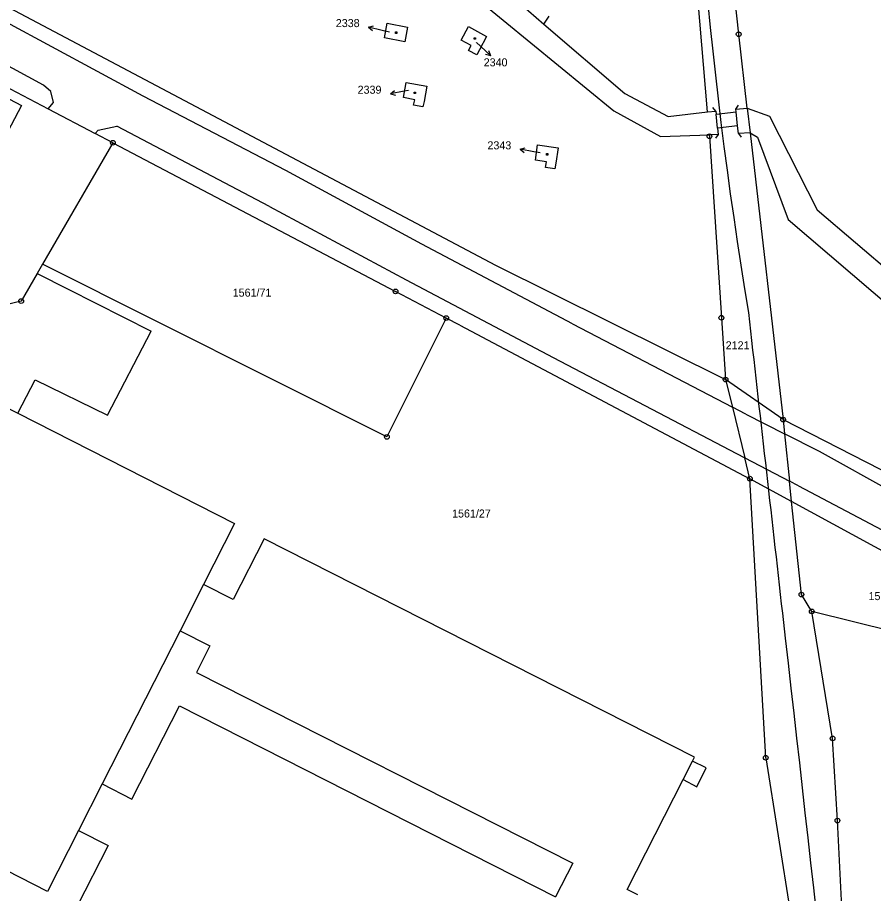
# Model space of a CAD drawing. Extents: x -795483 to -789093, y -1112258 to -1108741.
# Drawn here: x -792761.3 to -792579.5, y -1110577.6 to -1110391.5 of the extents above; entities that cross this region are included whole.
import ezdxf

# ---------------------------------------------------------------- set-up
doc = ezdxf.new("R2010")
doc.units = 0
for name, color, linetype in [('Komunikace', 7, 'Continuous'), ('Popis vodovodních řadů', 7, 'Continuous'), ('Vrstva 1', 7, 'Continuous'), ('Vrstva 10', 7, 'Continuous'), ('Vrstva 14', 7, 'Continuous'), ('Vrstva 15', 7, 'Continuous'), ('Vrstva 16', 7, 'Continuous'), ('Vrstva 2', 7, 'Continuous'), ('Vrstva 25', 7, 'Continuous'), ('Vrstva 28', 7, 'Continuous')]:
    doc.layers.add(name, color=color, linetype=linetype)

msp = doc.modelspace()

# ---------------------------------------------------------------- linework, layer by layer
at = {"layer": 'Komunikace'}
for p, q in [((-792682.33, -1110394.57), (-792683.89, -1110394.2)), ((-792663.85, -1110396.79), (-792663.02, -1110397.58)), ((-792678.29, -1110406.98), (-792679.19, -1110407.14)), ((-792650.34, -1110420.22), (-792651.65, -1110419.99))]:
    msp.add_line(p, q, dxfattribs=at)
at = {"layer": 'Popis vodovodních řadů'}
for p, q in [((-792613.01, -1110411.35), (-792613.66, -1110410.6)), ((-792608.74, -1110410.94), (-792608.23, -1110410.09)), ((-792612.51, -1110416.31), (-792613.08, -1110417.12)), ((-792608.23, -1110416.1), (-792607.66, -1110416.91))]:
    msp.add_line(p, q, dxfattribs=at)
at = {"layer": 'Vrstva 1'}
for p, q in [((-792608.17, -1110395.02), (-792615.38, -1110323.92)), ((-792614.81, -1110411.53), (-792620.21, -1110347.82)), ((-792681.61, -1110364.96), (-792649.52, -1110392.89)), ((-792780.58, -1110380.1), (-792659.8, -1110444.12)), ((-792666.12, -1110385.5), (-792634.65, -1110411.27)), ((-792649.52, -1110392.89), (-792648.42, -1110391.17)), ((-792683.39, -1110395.82), (-792682.79, -1110392.67)), ((-792682.79, -1110392.67), (-792678.49, -1110393.51)), ((-792678.49, -1110393.51), (-792679.09, -1110396.64)), ((-792667.12, -1110396.3), (-792665.58, -1110393.41)), ((-792665.58, -1110393.41), (-792661.7, -1110395.49)), ((-792649.52, -1110392.89), (-792632.37, -1110407.62)), ((-792679.09, -1110396.64), (-792683.39, -1110395.82)), ((-792661.7, -1110395.49), (-792663.23, -1110398.37)), ((-792606.36, -1110410.71), (-792608.17, -1110395.02)), ((-792781.4, -1110396.88), (-792754.82, -1110410.86)), ((-792665, -1110397.43), (-792667.12, -1110396.3)), ((-792665.56, -1110398.49), (-792665, -1110397.43)), ((-792663.79, -1110399.43), (-792665.56, -1110398.49)), ((-792663.23, -1110398.37), (-792663.79, -1110399.43)), ((-792679.35, -1110408.5), (-792678.76, -1110405.29)), ((-792678.76, -1110405.29), (-792674.41, -1110406.08)), ((-792674.41, -1110406.08), (-792674.99, -1110409.3)), ((-792676.97, -1110408.94), (-792679.35, -1110408.5)), ((-792632.37, -1110407.62), (-792623.11, -1110412.52)), ((-792677.19, -1110410.12), (-792676.97, -1110408.94)), ((-792675.21, -1110410.48), (-792677.19, -1110410.12)), ((-792674.99, -1110409.3), (-792675.21, -1110410.48)), ((-792608.74, -1110410.94), (-792606.36, -1110410.71)), ((-792606.36, -1110410.71), (-792601.62, -1110412.42)), ((-792606.36, -1110410.71), (-792605.76, -1110415.98)), ((-792754.82, -1110410.86), (-792744.86, -1110416.1)), ((-792634.65, -1110411.27), (-792624.78, -1110416.77)), ((-792623.11, -1110412.52), (-792614.81, -1110411.53)), ((-792614.81, -1110411.53), (-792613.01, -1110411.35)), ((-792613.01, -1110411.35), (-792612.94, -1110412.04)), ((-792612.94, -1110412.04), (-792608.68, -1110411.53)), ((-792608.68, -1110411.53), (-792608.74, -1110410.94)), ((-792601.62, -1110412.42), (-792591.51, -1110432.33)), ((-792741.07, -1110418.09), (-792744.86, -1110416.1)), ((-792612.51, -1110416.31), (-792614.4, -1110416.41)), ((-792608.39, -1110414.49), (-792612.65, -1110414.98)), ((-792612.65, -1110414.98), (-792612.51, -1110416.31)), ((-792608.23, -1110416.1), (-792608.39, -1110414.49)), ((-792605.76, -1110415.98), (-792608.23, -1110416.1)), ((-792605.76, -1110415.98), (-792604.19, -1110416.91)), ((-792605.76, -1110415.98), (-792598.74, -1110476.89)), ((-792741.07, -1110418.09), (-792756.01, -1110443.91)), ((-792741.07, -1110418.09), (-792681.03, -1110449.67)), ((-792624.78, -1110416.77), (-792614.4, -1110416.41)), ((-792614.4, -1110416.41), (-792614.37, -1110416.71)), ((-792614.37, -1110416.71), (-792611.85, -1110455.28)), ((-792604.19, -1110416.91), (-792597.68, -1110434.36)), ((-792651.35, -1110421.79), (-792650.87, -1110418.51)), ((-792650.87, -1110418.51), (-792646.52, -1110419.16)), ((-792646.52, -1110419.16), (-792647, -1110422.44)), ((-792648.99, -1110422.14), (-792651.35, -1110421.79)), ((-792649.17, -1110423.34), (-792648.99, -1110422.14)), ((-792647.18, -1110423.63), (-792649.17, -1110423.34)), ((-792647, -1110422.44), (-792647.18, -1110423.63)), ((-792591.51, -1110432.33), (-792497.5, -1110512.53)), ((-792597.68, -1110434.36), (-792501.08, -1110517.07)), ((-792756.01, -1110443.91), (-792757.16, -1110445.89)), ((-792682.88, -1110480.58), (-792756.01, -1110443.91)), ((-792659.8, -1110444.12), (-792610.94, -1110468.39)), ((-792757.16, -1110445.89), (-792760.54, -1110451.74)), ((-792757.16, -1110445.89), (-792750.58, -1110449.21)), ((-792750.58, -1110449.21), (-792732.96, -1110458.09)), ((-792670.27, -1110455.33), (-792681.03, -1110449.67)), ((-792760.54, -1110451.74), (-792783.32, -1110457.02)), ((-792670.27, -1110455.33), (-792682.88, -1110480.58)), ((-792667.41, -1110456.84), (-792670.27, -1110455.33)), ((-792611.85, -1110455.28), (-792610.94, -1110468.39)), ((-792667.41, -1110456.84), (-792605.8, -1110489.46)), ((-792742.2, -1110475.94), (-792732.96, -1110458.09)), ((-792761.23, -1110475.55), (-792757.59, -1110468.44)), ((-792757.59, -1110468.44), (-792742.2, -1110475.94)), ((-792610.94, -1110468.39), (-792609.51, -1110474.26)), ((-792768.36, -1110471.92), (-792761.23, -1110475.55)), ((-792761.23, -1110475.55), (-792715.21, -1110499)), ((-792609.51, -1110474.26), (-792606.89, -1110485.01)), ((-792598.74, -1110476.89), (-792553.17, -1110500.22)), ((-792598.74, -1110476.89), (-792598.42, -1110479.91)), ((-792598.42, -1110479.91), (-792597.37, -1110489.98)), ((-792605.8, -1110489.46), (-792606.89, -1110485.01)), ((-792602.43, -1110548.75), (-792605.8, -1110489.46)), ((-792596.92, -1110494.31), (-792605.8, -1110489.46)), ((-792596.92, -1110494.31), (-792597.37, -1110489.98)), ((-792521.65, -1110535.49), (-792596.92, -1110494.31)), ((-792594.86, -1110514.07), (-792596.92, -1110494.31)), ((-792715.21, -1110499), (-792721.79, -1110511.93)), ((-792708.94, -1110502.27), (-792715.49, -1110515.15)), ((-792617.55, -1110548.61), (-792708.94, -1110502.27)), ((-792721.79, -1110511.93), (-792726.81, -1110521.82)), ((-792715.49, -1110515.15), (-792721.79, -1110511.93)), ((-792592.65, -1110517.65), (-792594.86, -1110514.07)), ((-792521.65, -1110535.49), (-792592.65, -1110517.65)), ((-792588.22, -1110544.64), (-792592.65, -1110517.65)), ((-792726.81, -1110521.82), (-792743.32, -1110554.29)), ((-792587.19, -1110562.1), (-792588.22, -1110544.64)), ((-792617.98, -1110549.46), (-792617.55, -1110548.61)), ((-792615.07, -1110550.92), (-792617.98, -1110549.46)), ((-792602.43, -1110548.75), (-792592.15, -1110613.52)), ((-792617.03, -1110554.92), (-792615.07, -1110550.92)), ((-792631.85, -1110576.75), (-792619.99, -1110553.41)), ((-792619.99, -1110553.41), (-792617.03, -1110554.92)), ((-792743.32, -1110554.29), (-792748.36, -1110564.21)), ((-792585.02, -1110604.07), (-792587.19, -1110562.1)), ((-792748.36, -1110564.21), (-792742.08, -1110567.4)), ((-792742.08, -1110567.4), (-792748.62, -1110580.29)), ((-792629.58, -1110577.89), (-792631.85, -1110576.75))]:
    msp.add_line(p, q, dxfattribs=at)
msp.add_lwpolyline([(-792748.36, -1110564.21), (-792754.94, -1110577.15), (-792801.15, -1110553.55)], dxfattribs=at)
at = {"layer": 'Vrstva 10'}
for centre, radius, start, end in [((-791654.82, -1110295.97), 964.34, 179.75891, 189.43975), ((-568495.15, -1085164.41), 225533.35, 186.4382861, 186.4546222), ((-545938.95, -1082684.09), 248225.4, 186.4382139, 186.4776556)]:
    msp.add_arc(centre, radius, start, end, dxfattribs=at)
at = {"layer": 'Vrstva 16'}
for p, q in [((-792686.81, -1110393.51), (-792685.72, -1110393.25)), ((-792683.89, -1110394.2), (-792686.81, -1110393.51)), ((-792686.81, -1110393.51), (-792685.95, -1110394.23)), ((-792663.02, -1110397.58), (-792660.83, -1110399.64)), ((-792660.83, -1110399.64), (-792661.91, -1110399.31)), ((-792660.83, -1110399.64), (-792661.22, -1110398.59)), ((-792682.14, -1110407.67), (-792681.25, -1110407)), ((-792679.19, -1110407.14), (-792682.14, -1110407.67)), ((-792682.14, -1110407.67), (-792681.07, -1110407.98)), ((-792654.6, -1110419.48), (-792653.54, -1110419.16)), ((-792651.65, -1110419.99), (-792654.6, -1110419.48)), ((-792654.6, -1110419.48), (-792653.71, -1110420.14))]:
    msp.add_line(p, q, dxfattribs=at)
at = {"layer": 'Vrstva 2'}
for p, q in [((-792755.78, -1110405.83), (-792779.28, -1110393.19)), ((-792734.65, -1110408.19), (-792763.7, -1110392.48)), ((-792770.97, -1110404.57), (-792760.47, -1110410.2)), ((-792754.27, -1110407.23), (-792755.78, -1110405.83)), ((-792753.69, -1110409.5), (-792754.27, -1110407.23)), ((-792704.32, -1110423.95), (-792734.65, -1110408.19)), ((-792760.47, -1110410.2), (-792768.93, -1110426.16)), ((-792754.82, -1110410.86), (-792753.69, -1110409.5)), ((-792612.65, -1110414.98), (-792612.94, -1110412.04)), ((-792608.39, -1110414.49), (-792608.68, -1110411.53)), ((-792744.17, -1110415.42), (-792744.86, -1110416.1)), ((-792744.17, -1110415.42), (-792740.24, -1110414.55)), ((-792707.83, -1110431.64), (-792740.24, -1110414.55)), ((-792675.45, -1110439.61), (-792704.32, -1110423.95)), ((-792707.83, -1110431.64), (-792678.77, -1110447.22)), ((-792643.45, -1110456.57), (-792675.45, -1110439.61)), ((-792678.77, -1110447.22), (-792647.57, -1110463.72)), ((-792643.45, -1110456.57), (-792609.51, -1110474.26)), ((-792647.57, -1110463.72), (-792608.66, -1110484.08)), ((-792598.74, -1110476.89), (-792610.94, -1110468.39)), ((-792606.67, -1110475.74), (-792609.51, -1110474.26)), ((-792606.67, -1110475.74), (-792598.42, -1110479.91)), ((-792591.02, -1110483.65), (-792598.42, -1110479.91)), ((-792608.66, -1110484.08), (-792606.89, -1110485.01)), ((-792606.89, -1110485.01), (-792597.37, -1110489.98)), ((-792555.17, -1110503.69), (-792591.02, -1110483.65)), ((-792595.45, -1110490.98), (-792597.37, -1110489.98)), ((-792595.45, -1110490.98), (-792559.11, -1110510.27)), ((-792726.81, -1110521.82), (-792720.49, -1110525.01)), ((-792720.49, -1110525.01), (-792723.33, -1110530.62)), ((-792723.33, -1110530.62), (-792643.41, -1110571.15)), ((-792737.04, -1110557.56), (-792726.95, -1110537.73)), ((-792726.95, -1110537.73), (-792647.05, -1110578.32)), ((-792619.99, -1110553.41), (-792617.98, -1110549.46)), ((-792743.32, -1110554.29), (-792737.04, -1110557.56)), ((-792643.41, -1110571.15), (-792647.05, -1110578.32))]:
    msp.add_line(p, q, dxfattribs=at)
at = {"layer": 'Vrstva 25'}
for p, q in [((-792681.04, -1110394.55), (-792680.74, -1110394.55)), ((-792681.04, -1110394.85), (-792681.04, -1110394.55)), ((-792680.74, -1110394.85), (-792681.04, -1110394.85)), ((-792680.74, -1110394.55), (-792680.74, -1110394.85)), ((-792664.36, -1110395.76), (-792664.06, -1110395.76)), ((-792664.36, -1110396.06), (-792664.36, -1110395.76)), ((-792664.06, -1110395.76), (-792664.06, -1110396.06)), ((-792664.06, -1110396.06), (-792664.36, -1110396.06)), ((-792677.09, -1110407.34), (-792676.79, -1110407.34)), ((-792677.09, -1110407.64), (-792677.09, -1110407.34)), ((-792676.79, -1110407.64), (-792677.09, -1110407.64)), ((-792676.79, -1110407.34), (-792676.79, -1110407.64)), ((-792649.01, -1110420.4), (-792648.71, -1110420.4)), ((-792649.01, -1110420.7), (-792649.01, -1110420.4)), ((-792648.71, -1110420.7), (-792649.01, -1110420.7)), ((-792648.71, -1110420.4), (-792648.71, -1110420.7))]:
    msp.add_line(p, q, dxfattribs=at)
at = {"layer": 'Vrstva 28'}
for centre, radius in [((-792608.17, -1110395.02), 0.5), ((-792608.17, -1110395.02), 0.01), ((-792614.37, -1110416.71), 0.5), ((-792741.07, -1110418.09), 0.5), ((-792741.07, -1110418.09), 0.01), ((-792614.37, -1110416.71), 0.01), ((-792681.03, -1110449.67), 0.5), ((-792681.03, -1110449.67), 0.01), ((-792760.54, -1110451.74), 0.5), ((-792760.54, -1110451.74), 0.01), ((-792670.27, -1110455.33), 0.5), ((-792670.27, -1110455.33), 0.01), ((-792611.85, -1110455.28), 0.5), ((-792611.85, -1110455.28), 0.01), ((-792610.94, -1110468.39), 0.5), ((-792610.94, -1110468.39), 0.01), ((-792598.74, -1110476.89), 0.5), ((-792598.74, -1110476.89), 0.01), ((-792682.88, -1110480.58), 0.5), ((-792682.88, -1110480.58), 0.01), ((-792605.8, -1110489.46), 0.5), ((-792605.8, -1110489.46), 0.01), ((-792594.86, -1110514.07), 0.5), ((-792594.86, -1110514.07), 0.01), ((-792592.65, -1110517.65), 0.5), ((-792592.65, -1110517.65), 0.01), ((-792588.22, -1110544.64), 0.5), ((-792588.22, -1110544.64), 0.01), ((-792602.43, -1110548.75), 0.5), ((-792602.43, -1110548.75), 0.01), ((-792587.19, -1110562.1), 0.5), ((-792587.19, -1110562.1), 0.01)]:
    msp.add_circle(centre, radius, dxfattribs=at)

# ---------------------------------------------------------------- texts
at = {"layer": 'Vrstva 14'}
for s, p in [('1561/71', (-792715.62, -1110450.78)), ('2121', (-792610.93, -1110461.97)), ('1561/27', (-792669.03, -1110497.71)), ('1561/4', (-792580.6, -1110515.26))]:
    msp.add_text(s, height=1.7, dxfattribs=at).set_placement(p)
at = {"layer": 'Vrstva 15'}
for s, p in [('2338', (-792682.33, -1110394.57)), ('2340', (-792664.02, -1110396.79)), ('2339', (-792678.29, -1110406.98)), ('2343', (-792650.34, -1110420.22))]:
    msp.add_text(s, height=0.1, dxfattribs=at).set_placement(p)
at = {"layer": 'Vrstva 16'}
for s, p in [('2338', (-792693.72, -1110393.51)), ('2340', (-792662.32, -1110401.85)), ('2339', (-792689.09, -1110407.67)), ('2343', (-792661.52, -1110419.48))]:
    msp.add_text(s, height=1.7, dxfattribs=at).set_placement(p)

doc.saveas('drawing.dxf')
